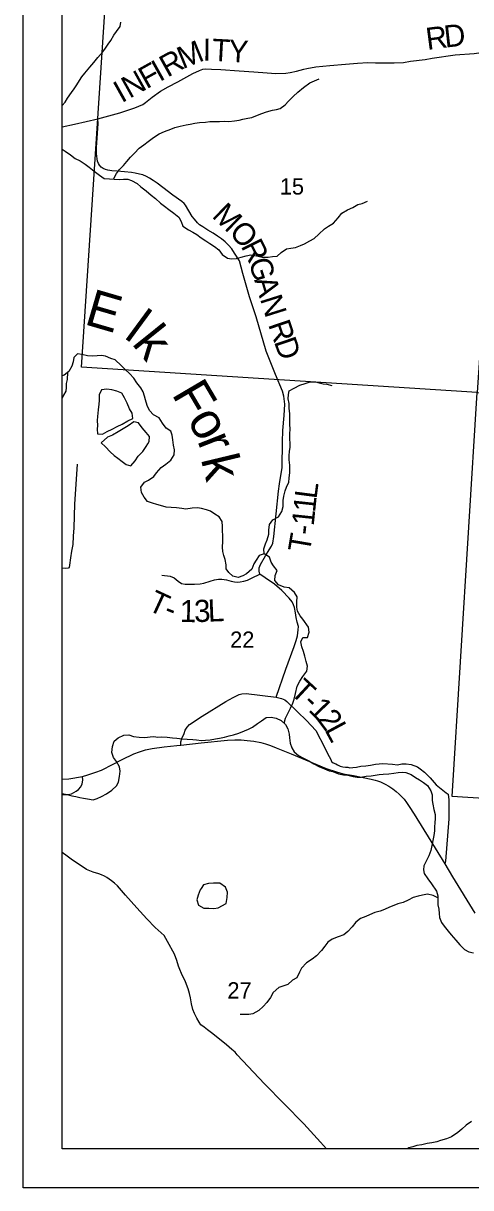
# Model space of a CAD drawing. Extents: x 0 to 34, y 0 to 22.
# Drawn here: x 23.417 to 24.565, y 14 to 16.992 of the extents above; entities that cross this region are included whole.
import ezdxf

# ---------------------------------------------------------------- set-up
doc = ezdxf.new("R2010")
doc.units = 0
for name, color, linetype in [('GM_X_City_Street', 7, 'Continuous'), ('GM_X_Minor_Lake', 7, 'Continuous'), ('GM_X_Minor_River', 7, 'Continuous'), ('GM_X_Minor_River_Text', 7, 'Continuous'), ('GM_X_Section', 7, 'Continuous'), ('GM_X_Section_Text', 7, 'Continuous'), ('GM_X_Township_Road', 7, 'Continuous'), ('GM_X_Township_Road_Text', 7, 'Continuous'), ('GM_X_US_Route', 7, 'Continuous'), ('SH_Data', 7, 'Continuous')]:
    doc.layers.add(name, color=color, linetype=linetype)

msp = doc.modelspace()

# ---------------------------------------------------------------- linework, layer by layer
at = {"layer": 'GM_X_City_Street'}
for points in [[(23.5167, 15.5925), (23.5259, 15.5921), (23.5325, 15.5922), (23.5354, 15.5935), (23.5362, 15.5994), (23.5391, 15.6185), (23.5416, 15.6351), (23.5445, 15.6523), (23.5459, 15.6742), (23.5472, 15.6951), (23.5488, 15.7563), (23.5561, 15.859)], [(23.5167, 15.0105), (23.5213, 15.0098), (23.5319, 15.01), (23.54, 15.0122), (23.5464, 15.015), (23.5527, 15.0189), (23.5585, 15.0231), (23.5642, 15.0302), (23.5679, 15.0372), (23.5699, 15.047), (23.569, 15.0564)], [(23.734, 14.6912), (23.7079, 14.7191), (23.6795, 14.7514), (23.6584, 14.7754), (23.651, 14.7824), (23.6432, 14.7887), (23.6375, 14.793), (23.6314, 14.797), (23.6255, 14.8004), (23.6178, 14.8035), (23.6104, 14.8066), (23.5963, 14.8111), (23.5791, 14.8177), (23.5703, 14.8236), (23.5431, 14.8419), (23.5291, 14.8517), (23.5167, 14.8611)]]:
    msp.add_lwpolyline(points, dxfattribs=at)
at = {"layer": 'GM_X_Minor_Lake'}
for points in [[(23.6607, 16.0446), (23.657, 16.046), (23.6441, 16.0498), (23.6313, 16.0516), (23.6177, 16.0497), (23.6113, 16.0368), (23.6113, 16.0228), (23.611, 16.0133), (23.6091, 15.9985), (23.6073, 15.981), (23.6066, 15.9712), (23.607, 15.9583), (23.6066, 15.9488), (23.6074, 15.9367)], [(23.6074, 15.9367), (23.6199, 15.9359), (23.6316, 15.9424), (23.6445, 15.9485), (23.6577, 15.9557), (23.6706, 15.9618), (23.6849, 15.9706), (23.6978, 15.9763), (23.6962, 15.9896), (23.6894, 16.0013), (23.6836, 16.0157), (23.6764, 16.029), (23.6699, 16.0411), (23.6607, 16.0446)], [(23.7363, 15.9109), (23.74, 15.9169), (23.7411, 15.9298), (23.7323, 15.94), (23.7221, 15.9521), (23.7126, 15.965), (23.7001, 15.968), (23.6861, 15.9577), (23.6732, 15.9493), (23.66, 15.9417), (23.6453, 15.9337), (23.6332, 15.928), (23.617, 15.9136)], [(23.617, 15.9136), (23.6276, 15.903), (23.6394, 15.8909), (23.6496, 15.881), (23.6591, 15.8746), (23.6705, 15.8659), (23.6804, 15.8583), (23.6925, 15.855), (23.7038, 15.8671), (23.7117, 15.8797), (23.7234, 15.8918), (23.7321, 15.904), (23.7363, 15.9109)], [(23.9379, 14.7304), (23.9398, 14.7452), (23.9406, 14.7596), (23.936, 14.7725), (23.9217, 14.7823), (23.905, 14.7824), (23.8926, 14.7812), (23.8793, 14.7779), (23.8734, 14.7687)], [(23.8734, 14.7687), (23.871, 14.765), (23.866, 14.7513), (23.8626, 14.7392), (23.8668, 14.726), (23.8804, 14.718), (23.8932, 14.718), (23.9061, 14.7172), (23.9167, 14.7191), (23.9379, 14.7304)]]:
    msp.add_lwpolyline(points, dxfattribs=at)
at = {"layer": 'GM_X_Minor_River'}
for points in [[(23.5167, 16.7807), (23.524, 16.7893), (23.53, 16.7992), (23.5402, 16.8136), (23.547, 16.8231), (23.5542, 16.8333), (23.5613, 16.8444), (23.5673, 16.8539), (23.5745, 16.8637), (23.5873, 16.8786), (23.5975, 16.8911), (23.6077, 16.904), (23.6209, 16.9181), (23.628, 16.928), (23.6345, 16.9382), (23.6416, 16.9477), (23.6495, 16.9606), (23.6559, 16.9701), (23.665, 16.9834), (23.6668, 16.994)], [(23.6485, 16.591), (23.6556, 16.6057), (23.6635, 16.6156), (23.6741, 16.6266), (23.6824, 16.6361), (23.6922, 16.6475), (23.702, 16.6581), (23.7144, 16.6703), (23.7261, 16.6794), (23.7375, 16.6878), (23.7511, 16.6977), (23.7654, 16.7072), (23.7794, 16.7137), (23.7957, 16.7198), (23.8059, 16.7236), (23.8191, 16.7271), (23.835, 16.7309), (23.8452, 16.7328), (23.8573, 16.7351), (23.8694, 16.7363), (23.8842, 16.7375), (23.8955, 16.739), (23.9099, 16.7394), (23.9201, 16.7394), (23.9322, 16.7399), (23.944, 16.7391), (23.9591, 16.7407), (23.9708, 16.743), (23.9807, 16.7449), (23.9932, 16.7476), (24.0038, 16.7499), (24.0177, 16.7556), (24.0295, 16.7602), (24.0412, 16.7644), (24.0567, 16.7682), (24.0665, 16.7701), (24.0764, 16.7728), (24.0892, 16.7819), (24.0979, 16.7914), (24.11, 16.8036), (24.1217, 16.8146), (24.136, 16.8268), (24.1526, 16.8382), (24.164, 16.8439), (24.1761, 16.8485)], [(23.5167, 16.6685), (23.5244, 16.6626), (23.5377, 16.6539), (23.5499, 16.6445), (23.5624, 16.6385), (23.5756, 16.6294), (23.5855, 16.6215), (23.5984, 16.6116), (23.6121, 16.601), (23.6242, 16.5931), (23.6382, 16.5916), (23.6496, 16.5909), (23.6625, 16.5905), (23.6742, 16.591), (23.6848, 16.591), (23.6943, 16.588), (23.7091, 16.5797), (23.7185, 16.5717), (23.7318, 16.5611), (23.7451, 16.5502), (23.7557, 16.5415), (23.769, 16.5294), (23.7789, 16.5214), (23.7903, 16.5135), (23.8032, 16.5033), (23.8161, 16.4938), (23.8218, 16.4825), (23.8264, 16.4707), (23.8412, 16.4605), (23.8518, 16.4545), (23.862, 16.4485), (23.873, 16.4401), (23.8852, 16.4326), (23.8954, 16.4258), (23.9079, 16.4182), (23.9189, 16.4099), (23.9273, 16.3978), (23.9406, 16.388), (23.9516, 16.3861), (23.9641, 16.3873), (23.9758, 16.3903), (23.989, 16.3945), (24.0007, 16.3965), (24.0106, 16.3953), (24.0201, 16.3931), (24.0303, 16.3908), (24.0458, 16.3909), (24.0568, 16.392), (24.0685, 16.3936), (24.0787, 16.4027), (24.0927, 16.4122), (24.104, 16.4134), (24.1158, 16.4153), (24.1286, 16.4203), (24.1384, 16.4252), (24.1524, 16.4325), (24.1638, 16.4386), (24.1755, 16.45), (24.1898, 16.4633), (24.2, 16.4705), (24.2132, 16.4781), (24.2253, 16.4918), (24.2347, 16.5036), (24.2491, 16.512), (24.2627, 16.5181), (24.2759, 16.5261), (24.2869, 16.5284), (24.3005, 16.5348)], [(24.134, 15.4609), (24.1272, 15.4689), (24.1203, 15.4814), (24.1191, 15.4916), (24.1191, 15.5052), (24.1198, 15.5178), (24.1126, 15.5295), (24.0997, 15.5412), (24.0868, 15.5431), (24.072, 15.5487), (24.0621, 15.5601), (24.0636, 15.573), (24.0681, 15.5855), (24.0594, 15.5976), (24.0533, 15.6075), (24.0491, 15.6203), (24.0354, 15.6287), (24.0226, 15.6241), (24.0146, 15.6119), (24.0086, 15.6024), (24.0037, 15.5895), (23.9898, 15.5774), (23.98, 15.572), (23.9686, 15.5678), (23.955, 15.5708), (23.944, 15.5803), (23.9379, 15.5901), (23.9378, 15.6), (23.9351, 15.6136), (23.9313, 15.6239), (23.9294, 15.6341), (23.9282, 15.6458), (23.9289, 15.6599), (23.9293, 15.6747), (23.9281, 15.6883), (23.9284, 15.6989), (23.9276, 15.7118), (23.92, 15.7232), (23.9083, 15.7304), (23.8969, 15.7379), (23.8874, 15.7417), (23.8745, 15.7447), (23.8636, 15.7465), (23.8499, 15.7458), (23.834, 15.7431), (23.8234, 15.7446), (23.8102, 15.7464), (23.7965, 15.7475), (23.7833, 15.7486), (23.7693, 15.7528), (23.7598, 15.7554), (23.7488, 15.7588), (23.7352, 15.7633), (23.7272, 15.7739), (23.72, 15.786), (23.7188, 15.7997), (23.7282, 15.8126), (23.7384, 15.8175), (23.752, 15.827), (23.7588, 15.8369), (23.7705, 15.8502), (23.7826, 15.859), (23.7954, 15.8692), (23.8044, 15.8829), (23.8048, 15.8958), (23.8021, 15.9076), (23.8005, 15.9212), (23.7993, 15.9337), (23.7955, 15.9439), (23.7834, 15.9515), (23.7743, 15.964), (23.7659, 15.978), (23.7507, 15.9852), (23.7408, 15.9969), (23.7347, 16.0098), (23.7305, 16.0242), (23.7282, 16.0337), (23.7248, 16.0443), (23.7187, 16.0552), (23.7081, 16.0681), (23.7005, 16.0795), (23.6894, 16.092), (23.6773, 16.1033), (23.6678, 16.1124), (23.6526, 16.1268), (23.6416, 16.1305), (23.628, 16.1366), (23.6177, 16.1384), (23.6064, 16.1376), (23.5939, 16.1365), (23.5814, 16.1372), (23.567, 16.1402), (23.5556, 16.1424), (23.5462, 16.1326), (23.5444, 16.1219), (23.5414, 16.1109), (23.5338, 16.0973), (23.5214, 16.0878), (23.5167, 16.0855)], [(23.53, 16.0944), (23.5294, 16.0768), (23.5267, 16.0658), (23.5264, 16.0559), (23.5261, 16.0464), (23.52, 16.0358), (23.5167, 16.0288)], [(24.0349, 15.6285), (24.0339, 15.6415), (24.0384, 15.6545), (24.0425, 15.6647), (24.0474, 15.6791), (24.0473, 15.689), (24.0488, 15.7042), (24.0575, 15.7159), (24.0718, 15.7239), (24.0809, 15.7372), (24.0838, 15.7505), (24.0842, 15.7657), (24.0853, 15.777), (24.089, 15.7903), (24.0928, 15.8002), (24.0984, 15.8127), (24.0995, 15.8226), (24.101, 15.8374), (24.1013, 15.8469), (24.1009, 15.8567), (24.0994, 15.8704), (24.0997, 15.8802), (24.1004, 15.892), (24.1019, 15.9015), (24.1015, 15.9113), (24.1011, 15.925), (24.101, 15.9364), (24.1018, 15.9492), (24.1013, 15.9618), (24.1013, 15.9747), (24.1009, 15.9887), (24.0997, 16.002), (24.0989, 16.0145), (24.097, 16.0266), (24.0973, 16.0376), (24.0992, 16.0471), (24.1124, 16.0543), (24.1267, 16.0619), (24.1404, 16.0665), (24.1536, 16.07), (24.1665, 16.0708), (24.1763, 16.0681), (24.1862, 16.0651), (24.196, 16.064), (24.2085, 16.061)], [(24.0867, 15.1933), (24.0895, 15.2062), (24.1024, 15.2319), (24.1089, 15.2452), (24.1123, 15.255), (24.1157, 15.2698), (24.1196, 15.2887), (24.1264, 15.3016), (24.1347, 15.3137), (24.1446, 15.327), (24.1461, 15.3395), (24.1427, 15.3516), (24.1397, 15.3652), (24.1363, 15.3778), (24.1322, 15.3899), (24.1296, 15.4024), (24.1341, 15.4134), (24.1466, 15.4137), (24.1504, 15.427), (24.1489, 15.4399), (24.134, 15.4609)], [(23.9454, 15.1613), (23.956, 15.1639), (23.9704, 15.1681), (23.9844, 15.1741), (23.995, 15.1782), (24.0052, 15.1832), (24.018, 15.1922), (24.0279, 15.1994), (24.04, 15.2077), (24.0529, 15.2089), (24.0657, 15.2062), (24.0786, 15.2001), (24.0903, 15.1902), (24.0956, 15.1785), (24.0989, 15.1656), (24.1001, 15.1554), (24.1019, 15.1421), (24.1061, 15.13), (24.1125, 15.1201), (24.1234, 15.1106), (24.1359, 15.1038), (24.1495, 15.0965), (24.1623, 15.0889), (24.1775, 15.0813), (24.1903, 15.076), (24.2016, 15.0711), (24.2115, 15.0695), (24.2262, 15.0631), (24.2387, 15.0604), (24.2497, 15.0596), (24.2636, 15.0566), (24.2735, 15.0547), (24.2833, 15.055), (24.2969, 15.0573), (24.3102, 15.0584), (24.32, 15.0603), (24.3306, 15.0618), (24.3408, 15.0625), (24.3552, 15.0636), (24.3677, 15.0651), (24.379, 15.067), (24.3892, 15.0674), (24.3991, 15.0666), (24.4127, 15.0613), (24.4236, 15.0537), (24.4342, 15.048), (24.4444, 15.0411), (24.4542, 15.0332), (24.4633, 15.0195), (24.4663, 15.0097), (24.4666, 14.9949), (24.4678, 14.9854), (24.4704, 14.9714), (24.4745, 14.9589), (24.4745, 14.9486), (24.4737, 14.9373), (24.4726, 14.9274), (24.4722, 14.9172), (24.471, 14.9047), (24.468, 14.8918), (24.4657, 14.8789), (24.4634, 14.8664), (24.4577, 14.8524), (24.4516, 14.8407), (24.4452, 14.827), (24.4444, 14.8168), (24.4463, 14.8069), (24.4553, 14.7933), (24.4644, 14.7808), (24.478, 14.7618), (24.4806, 14.75), (24.4806, 14.7398), (24.4813, 14.7266), (24.4832, 14.7159), (24.4843, 14.7042), (24.4854, 14.6943), (24.4907, 14.6814), (24.4975, 14.6716), (24.5077, 14.6594), (24.5156, 14.6496), (24.5269, 14.6363), (24.5379, 14.6238), (24.5496, 14.6124), (24.5602, 14.6059), (24.573, 14.6033)], [(23.5167, 15.0132), (23.5295, 15.0099), (23.5412, 15.0065), (23.5514, 15.005), (23.5616, 15.0027), (23.5715, 15.0008), (23.5813, 14.9992), (23.5957, 14.9969), (23.6062, 15), (23.6172, 15.0052), (23.6305, 15.0117), (23.6437, 15.0215), (23.6562, 15.0325), (23.6615, 15.0423), (23.6638, 15.0567), (23.665, 15.0704), (23.6639, 15.081), (23.6556, 15.0954), (23.6484, 15.1056), (23.6439, 15.1181), (23.6458, 15.1333), (23.65, 15.1473), (23.6606, 15.156), (23.6746, 15.1628), (23.6875, 15.1639), (23.6999, 15.1594), (23.7143, 15.1578), (23.729, 15.1563), (23.7423, 15.1585), (23.7521, 15.1589), (23.7619, 15.1578), (23.7722, 15.1581), (23.7858, 15.1573), (23.7998, 15.1554), (23.8107, 15.1546), (23.8247, 15.1535), (23.8372, 15.1527), (23.8516, 15.1519), (23.8618, 15.1504), (23.8743, 15.1489), (23.8841, 15.1496), (23.8962, 15.1504), (23.9098, 15.153), (23.9204, 15.1549), (23.9333, 15.1579), (23.9454, 15.1613)], [(24.4806, 14.7444), (24.4689, 14.7508), (24.4549, 14.7543), (24.4413, 14.752), (24.4307, 14.749), (24.4178, 14.746), (24.4046, 14.7384), (24.3917, 14.7331), (24.3785, 14.729), (24.3679, 14.7248), (24.3569, 14.7211), (24.3444, 14.715), (24.3327, 14.7101), (24.3194, 14.7067), (24.3058, 14.7014), (24.296, 14.6969), (24.2823, 14.692), (24.2702, 14.6825), (24.2611, 14.67), (24.2498, 14.6579), (24.2395, 14.65), (24.2255, 14.6443), (24.2096, 14.6383), (24.199, 14.6307), (24.1911, 14.6209), (24.182, 14.6091), (24.1691, 14.5955), (24.1585, 14.5868), (24.1441, 14.5781), (24.1312, 14.5637), (24.1259, 14.5535), (24.1187, 14.5395), (24.1077, 14.5331), (24.0956, 14.5221), (24.0827, 14.5176), (24.0729, 14.5142), (24.0585, 14.5013), (24.0513, 14.4888), (24.0422, 14.476), (24.0324, 14.4654), (24.0214, 14.4551), (24.0059, 14.4468), (23.9956, 14.4453), (23.9858, 14.4446), (23.9733, 14.4454)], [(24.5674, 14.1697), (24.5538, 14.1603), (24.5424, 14.1508), (24.5322, 14.1421), (24.5163, 14.1311), (24.5034, 14.1259), (24.4883, 14.121), (24.4781, 14.1176), (24.4652, 14.1157), (24.4535, 14.1138), (24.4402, 14.11), (24.427, 14.1085), (24.4171, 14.1051), (24.4069, 14.1025), (24.403, 14.1)]]:
    msp.add_lwpolyline(points, dxfattribs=at)
at = {"layer": 'GM_X_Section'}
for points in [[(24.6497, 17.049), (24.5822, 16.0431), (23.5665, 16.1079), (23.6339, 17.1388)], [(25.5991, 15.9654), (25.5272, 14.9411), (24.518, 15.0047), (24.5822, 16.0431)]]:
    msp.add_lwpolyline(points, close=True, dxfattribs=at)
at = {"layer": 'GM_X_Township_Road'}
for points in [[(24.1366, 16.8734), (24.1444, 16.8754), (24.1681, 16.8798), (24.2036, 16.8832), (24.244, 16.8868), (24.2751, 16.8889), (24.3013, 16.8907), (24.3206, 16.8903), (24.3459, 16.8896), (24.369, 16.89), (24.3931, 16.891), (24.4105, 16.8939), (24.4483, 16.8989), (24.4664, 16.9016), (24.5257, 16.9105), (24.5742, 16.9142), (24.6152, 16.9196), (24.6642, 16.929), (24.6972, 16.9354), (24.7297, 16.9455), (24.7799, 16.965), (24.8281, 16.9828), (24.8527, 16.9918)], [(23.5167, 16.7255), (23.5484, 16.732), (23.6078, 16.7462), (23.6641, 16.7617), (23.7034, 16.7742), (23.7136, 16.7785), (23.7236, 16.7831), (23.7303, 16.7883), (23.7475, 16.802), (23.7688, 16.8175), (23.7887, 16.8287), (23.8132, 16.8415), (23.8518, 16.8622), (23.8687, 16.87), (23.8778, 16.8736), (23.8856, 16.8745), (23.8999, 16.8738), (23.9241, 16.8727), (23.9711, 16.869), (24.0083, 16.8665), (24.0424, 16.8642), (24.065, 16.8629), (24.0906, 16.8631), (24.1022, 16.8647), (24.1179, 16.8686), (24.1366, 16.8734)], [(24.0661, 15.2605), (24.0911, 15.3324), (24.1119, 15.3907), (24.1174, 15.4062), (24.1203, 15.4177), (24.1218, 15.4258), (24.1227, 15.4336), (24.1229, 15.4415), (24.1201, 15.4532), (24.1176, 15.4649), (24.1154, 15.4767), (24.1134, 15.4904), (24.1106, 15.4977), (24.1072, 15.5054), (24.0995, 15.5142), (24.0801, 15.5346), (24.0615, 15.5507), (24.0374, 15.5669), (24.0241, 15.5762), (24.0226, 15.5843), (24.0224, 15.5923), (24.0257, 15.6014), (24.0383, 15.6235), (24.0479, 15.6385), (24.0537, 15.6478), (24.0573, 15.6557), (24.06, 15.6734), (24.0723, 15.7897), (24.0743, 15.8085), (24.0812, 15.8504), (24.0821, 15.9166), (24.0829, 15.945), (24.0865, 15.984), (24.0878, 16.0131), (24.0856, 16.0335), (24.0818, 16.0467), (24.0646, 16.0889), (24.0403, 16.1491), (24.0142, 16.2373), (23.9976, 16.2888), (23.9801, 16.3491), (23.9715, 16.3809), (23.9592, 16.4008), (23.9518, 16.4122), (23.9435, 16.4211), (23.9347, 16.4298), (23.9252, 16.4379), (23.9157, 16.4449), (23.904, 16.4525), (23.8908, 16.4603), (23.8776, 16.4684), (23.869, 16.4741), (23.8636, 16.4789), (23.856, 16.4879), (23.8502, 16.4951), (23.8416, 16.51), (23.8331, 16.5242), (23.8294, 16.5285), (23.8241, 16.5337), (23.8002, 16.5503), (23.7753, 16.5693), (23.7606, 16.5808), (23.7503, 16.5876), (23.7404, 16.5938), (23.7326, 16.5979), (23.7234, 16.6018), (23.7147, 16.6043), (23.704, 16.6064), (23.6945, 16.6078), (23.6762, 16.6095), (23.6574, 16.6115), (23.6436, 16.6127), (23.6337, 16.6138), (23.628, 16.6156), (23.6214, 16.6189), (23.6169, 16.6222), (23.6127, 16.6272), (23.6099, 16.6317), (23.6076, 16.6371), (23.6064, 16.6436), (23.605, 16.6566), (23.605, 16.6727), (23.6073, 16.7089), (23.6085, 16.7337), (23.6078, 16.7462)], [(23.7727, 15.574), (23.794, 15.5715), (23.8037, 15.5667), (23.8144, 15.558), (23.8231, 15.5522), (23.8327, 15.5503), (23.856, 15.5505), (23.8706, 15.5511), (23.8802, 15.5534), (23.8968, 15.5586), (23.9078, 15.5617), (23.9178, 15.5638), (23.9264, 15.5636), (23.938, 15.5615), (23.9507, 15.5582), (23.9591, 15.5563), (23.9668, 15.5557), (23.9738, 15.5563), (23.9826, 15.558), (23.992, 15.5607), (24.0044, 15.5669), (24.0241, 15.5762)], [(23.8208, 15.1372), (23.8208, 15.1453), (23.8234, 15.1538), (23.8296, 15.1665), (23.8323, 15.1752), (23.8374, 15.1832), (23.8438, 15.1902), (23.876, 15.2114), (23.937, 15.249), (23.9554, 15.2594), (23.964, 15.2641), (23.9711, 15.2674), (23.9775, 15.2689), (23.989, 15.2698), (24.0661, 15.2605)], [(24.0661, 15.2605), (24.0798, 15.2568), (24.088, 15.2535), (24.0933, 15.2494), (24.1206, 15.2229), (24.1442, 15.2), (24.1674, 15.1748), (24.191, 15.1299), (24.1974, 15.1157), (24.206, 15.0999), (24.2082, 15.0952), (24.2121, 15.0913), (24.219, 15.0888), (24.2231, 15.086), (24.23, 15.0833), (24.2368, 15.0809), (24.2441, 15.0803), (24.25, 15.0803), (24.2553, 15.0783), (24.2626, 15.0792), (24.2723, 15.0807), (24.2834, 15.0829), (24.2964, 15.0838), (24.308, 15.0856), (24.321, 15.0882), (24.3402, 15.0899), (24.3649, 15.0884), (24.3771, 15.0867), (24.3885, 15.0888), (24.3993, 15.0886), (24.4128, 15.0873), (24.4286, 15.0809), (24.4357, 15.0763), (24.4472, 15.0673), (24.461, 15.0527), (24.4765, 15.0353), (24.4853, 15.0285), (24.5025, 15.0145), (24.5078, 15.0108), (24.5091, 14.9962), (24.5089, 14.9815), (24.5093, 14.9478), (24.5007, 14.8386), (24.4987, 14.8324)], [(24.1952, 14.1), (24.1797, 14.117), (24.137, 14.1638), (24.0364, 14.2668), (23.9656, 14.3418), (23.9606, 14.3479), (23.9525, 14.3555), (23.9388, 14.3673), (23.9032, 14.395), (23.8897, 14.4058), (23.8808, 14.4126), (23.8727, 14.4187), (23.8681, 14.4253), (23.8625, 14.4353), (23.8562, 14.4475), (23.852, 14.458), (23.8489, 14.4724), (23.8463, 14.488), (23.8435, 14.4992), (23.8396, 14.5109), (23.8328, 14.5286), (23.823, 14.5504), (23.8184, 14.5609), (23.8149, 14.5691), (23.8112, 14.5838), (23.8053, 14.6001), (23.787, 14.6328), (23.7785, 14.6476), (23.7554, 14.6686), (23.734, 14.6912)]]:
    msp.add_lwpolyline(points, dxfattribs=at)
at = {"layer": 'GM_X_US_Route'}
for points in [[(23.8105, 15.1361), (23.8208, 15.1372), (23.8737, 15.1427), (23.941, 15.1499), (23.9595, 15.1508), (23.9762, 15.1504), (23.9912, 15.1492), (24.0087, 15.147), (24.0263, 15.1437), (24.0382, 15.1405), (24.051, 15.1362), (24.0658, 15.1303), (24.1041, 15.1144), (24.194, 15.0772), (24.2209, 15.0684), (24.2379, 15.0635), (24.2642, 15.0589), (24.3102, 15.05), (24.3197, 15.0474), (24.3263, 15.0454), (24.334, 15.0425), (24.3457, 15.037), (24.355, 15.0317), (24.3653, 15.0251), (24.3739, 15.0181), (24.3819, 15.0112), (24.3879, 15.0049), (24.3947, 14.998), (24.4006, 14.9897), (24.407, 14.9793), (24.4202, 14.9594), (24.4987, 14.8324), (24.5188, 14.7985), (24.5763, 14.705)], [(23.5167, 15.05), (23.5332, 15.0503), (23.569, 15.0564), (23.5825, 15.0605), (23.6028, 15.0672), (23.6176, 15.0726), (23.6471, 15.0879), (23.6701, 15.1002), (23.7006, 15.1144), (23.7151, 15.1201), (23.73, 15.1246), (23.7474, 15.1281), (23.7786, 15.1327), (23.8105, 15.1361)]]:
    msp.add_lwpolyline(points, dxfattribs=at)
at = {"layer": 'SH_Data'}
for points in [[(23.4167, 21), (30.4167, 21), (30.4167, 14), (23.4167, 14)], [(23.5167, 20.9), (30.3167, 20.9), (30.3167, 14.1), (23.5167, 14.1)]]:
    msp.add_lwpolyline(points, close=True, dxfattribs=at)

# ---------------------------------------------------------------- texts
at = {"layer": 'GM_X_Minor_River_Text'}
for s, height, rotation, p in [('E', 0.0947, 343.7189, (23.5706, 16.2192)), ('l', 0.0947, 323.7178, (23.6729, 16.1847)), ('k', 0.0947, 308.7181, (23.6937, 16.1685)), ('Fo', 0.09471, 300.5019, (23.7963, 16.039)), ('r', 0.0947, 291.5028, (23.8626, 15.9198)), ('k', 0.0947, 283.5038, (23.8724, 15.8725))]:
    msp.add_text(s, height=height, rotation=rotation, dxfattribs=at).set_placement(p)
at = {"layer": 'GM_X_Section_Text'}
for s, p in [('15', (24.0752, 16.5515)), ('22', (23.9477, 15.3871)), ('27', (23.9407, 14.486))]:
    msp.add_text(s, height=0.04186, rotation=0, dxfattribs=at).set_placement(p)
at = {"layer": 'GM_X_Township_Road_Text'}
for s, rotation, p in [('R', 7.4876, (24.454, 16.9228)), ('D', 6.3772, (24.5, 16.9289)), ('M', 22.2111, (23.8261, 16.8735)), ('I', 359.1725, (23.8773, 16.8957)), ('T', 356.8356, (23.9, 16.8954)), ('Y', 356.6686, (23.9424, 16.893)), ('R', 29.0618, (23.7869, 16.8516)), ('F', 29.1626, (23.7331, 16.8216)), ('I', 29.1703, (23.7666, 16.8402)), ('N', 29.1654, (23.6894, 16.7972)), ('I', 29.163, (23.669, 16.7858)), ('M', 315.9983, (23.8989, 16.4947)), ('O', 312.8616, (23.9427, 16.4524)), ('R', 296.6035, (23.9743, 16.4193)), ('G', 287.3786, (23.9943, 16.3798)), ('A', 286.8451, (24.0092, 16.3322)), ('N', 287.5069, (24.0239, 16.2837)), ('R', 288.8039, (24.0448, 16.218)), ('D', 288.9065, (24.0599, 16.1737)), ('L', 82.5911, (24.1694, 15.7679)), ('1', 83.9207, (24.1657, 15.7335)), ('1', 83.995, (24.1621, 15.6987)), ('T', 80.3939, (24.152, 15.6297)), ('-', 83.946, (24.1596, 15.6754)), ('T', 335.2329, (23.7328, 15.4856)), ('1', 359.0172, (23.818, 15.4535)), ('3', 1.9289, (23.8561, 15.4529)), ('L', 2.3166, (23.8915, 15.4541)), ('-', 338.1589, (23.7743, 15.4666)), ('T', 317.2609, (24.0994, 15.2709)), ('-', 315.6171, (24.1302, 15.2424)), ('1', 314.3369, (24.1465, 15.2264)), ('2', 306.5952, (24.1695, 15.2032)), ('L', 298.3385, (24.189, 15.1771))]:
    msp.add_text(s, height=0.0568, rotation=rotation, dxfattribs=at).set_placement(p)

doc.saveas('drawing.dxf')
